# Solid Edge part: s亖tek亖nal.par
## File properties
Author: Türk
Template: iso part.par
Last saved by: Türk
Revision: 10
Application: Solid Edge
Accuracy: 0,990
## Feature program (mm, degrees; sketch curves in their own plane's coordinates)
base feature "unnamed BaseFeature 1"
thread "unnamed Thread 1"
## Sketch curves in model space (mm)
circle centre (240, 245, 0) radius 11.547
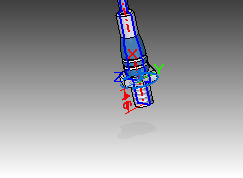
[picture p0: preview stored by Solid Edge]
